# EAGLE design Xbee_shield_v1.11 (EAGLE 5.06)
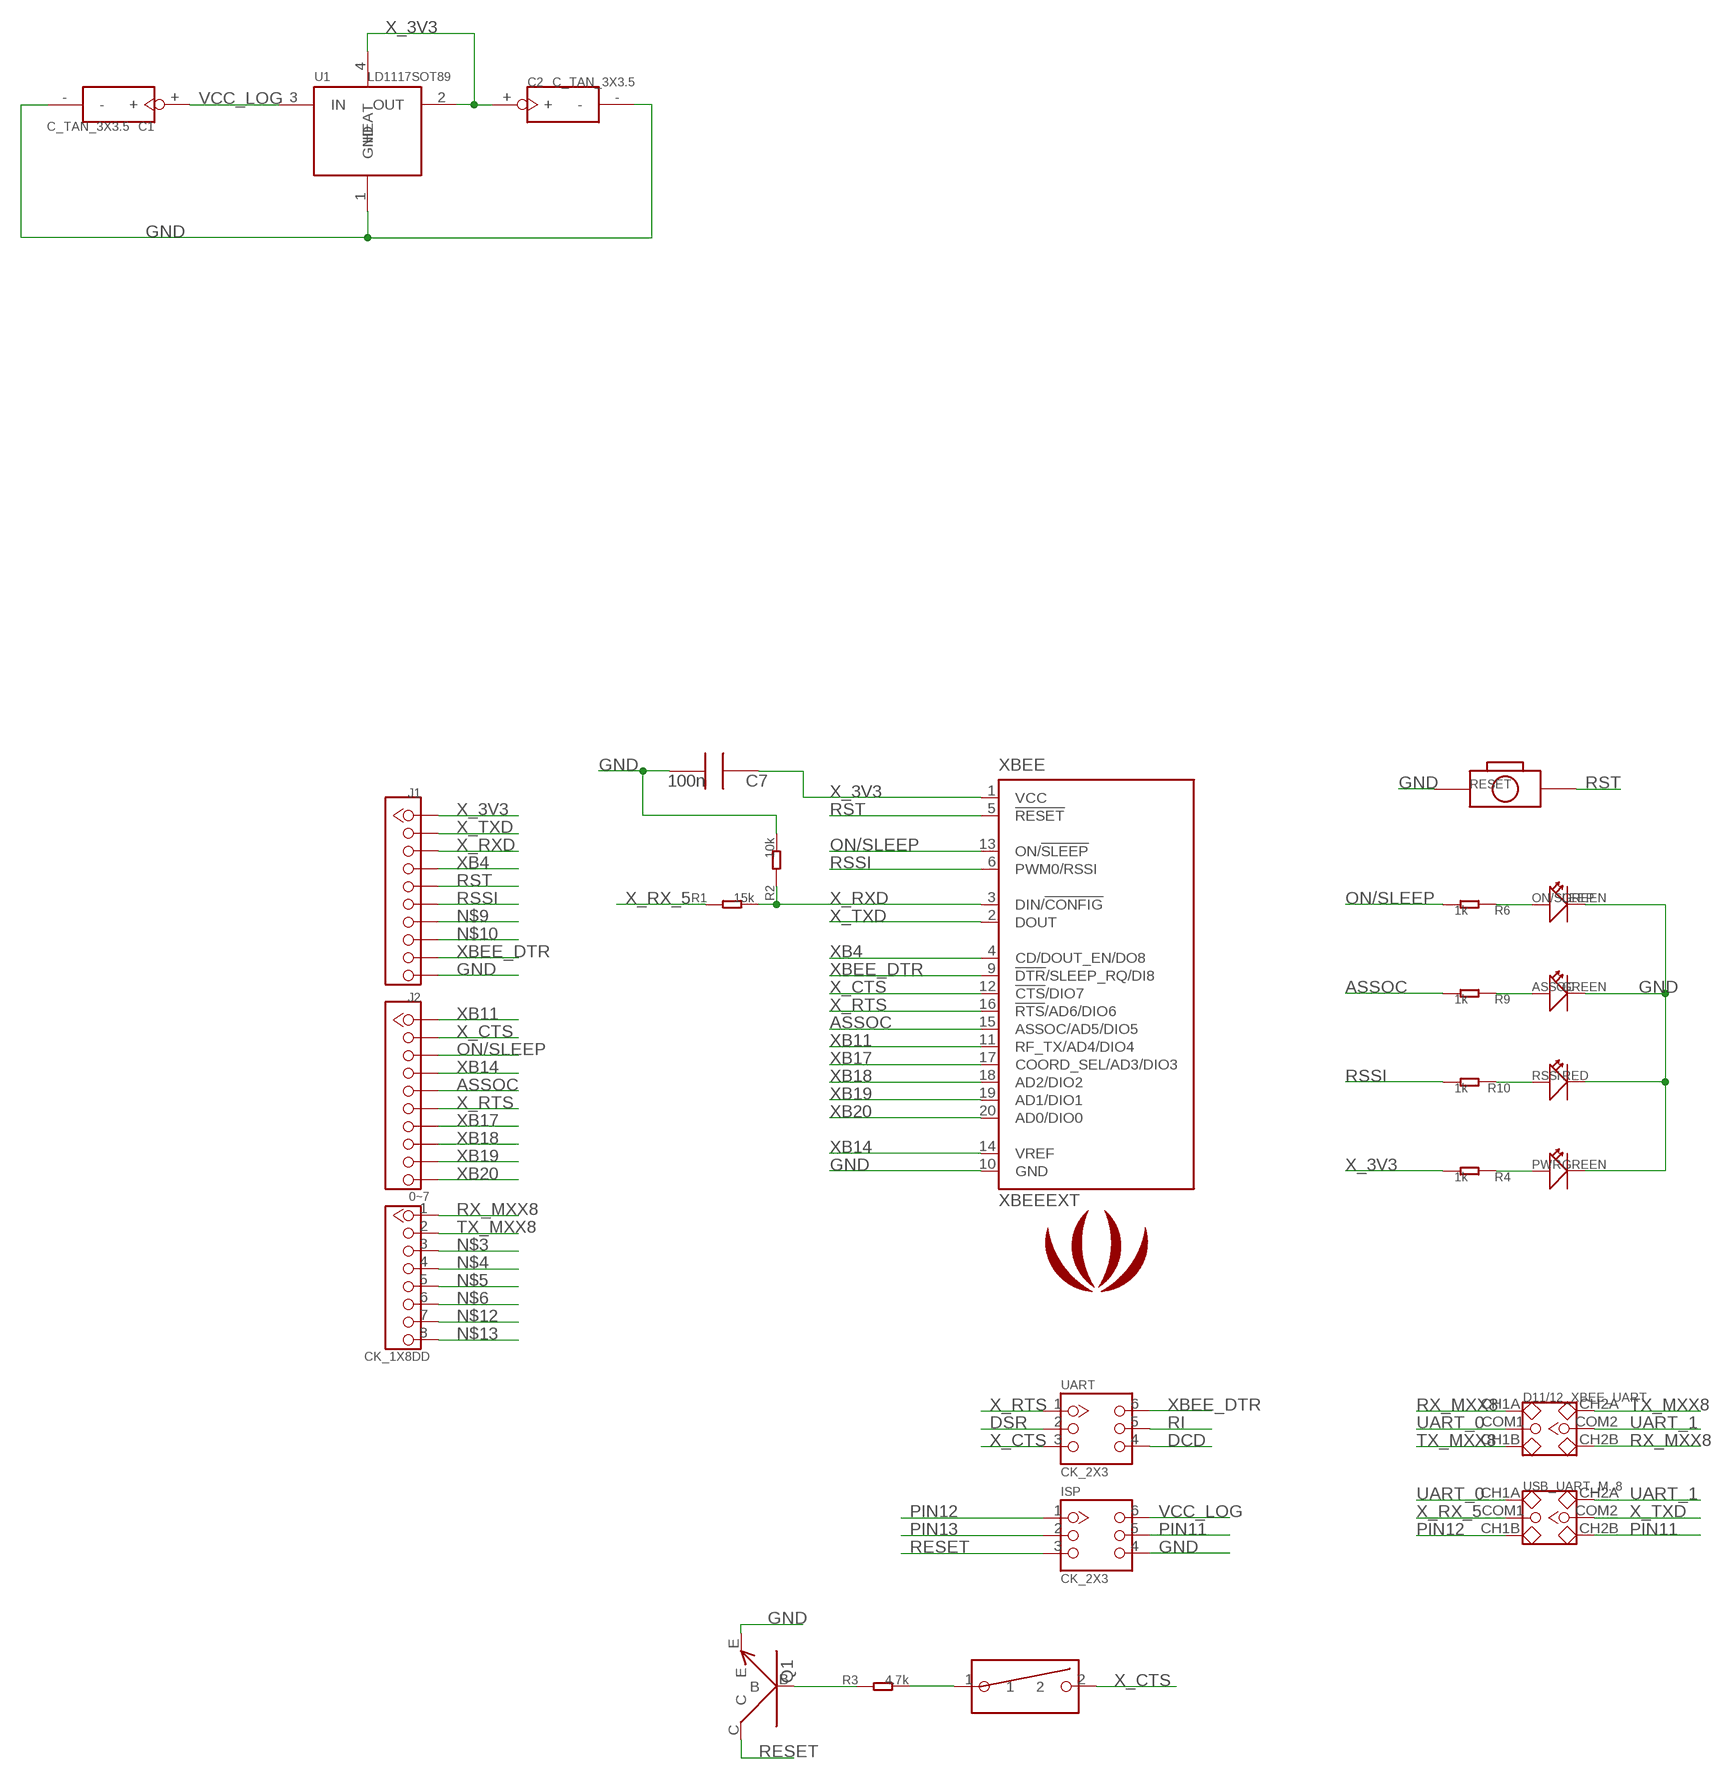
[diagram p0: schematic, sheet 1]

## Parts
0~7  CK_1X8DD  [CK_1X8]
ASSOC  GREEN  LED0603  [LED0603]
C1  C_TAN_3X3.5  [C_TAN_3X3.5]
C2  C_TAN_3X3.5  [C_TAN_3X3.5]
C7  100n  C0603  [0603]
D11/12_XBEE_UART  2.54SW_2CH  [2.54SW_2CH]
ISP  CK_2X3  [CK_2X3_THIN]
J1  CK1X10DD  [CK1X10]
J2  CK1X10DD  [CK1X10]
JP1  SMD_JP  [JP]
LOGO1  LOGO_COPPER200X166  [LOGO_COPPER]
ON/SLEEP  GREEN  LED0603  [LED0603]
PWR  GREEN  LED0603  [LED0603]
Q1  NPN_9013  [SOT23]
R1  15k  R0603  [0603]
R2  10k  R0603  [0603]
R3  4.7k  R0603  [0603]
R4  1k  R0603  [0603]
R6  1k  R0603  [0603]
R9  1k  R0603  [0603]
R10  1k  R0603  [0603]
RESET  BOTTON_1  BOTTON_1_DP  [BTN_5.0_RST]
RSSI  RED  LED0603  [LED0603]
U1  LD1117SOT89  [SOT89]
UART  CK_2X3  [CK_2X3_THIN]
USB_UART_M..8  2.54SW_2CH  [2.54SW_2CH]
XBEE  XBEEEXT  [XBEE_PLUG]

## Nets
ASSOC: J2.5 R9.2 XBEE.15(ASSOC/AD5/DIO5)
DCD: UART.4
DSR: UART.2
GND: ASSOC.2(-) C1.- C2.- C7.2 ISP.4 J1.10 ON/SLEEP.2(-) PWR.2(-) Q1.E R2.2 RESET.P$1 RSSI.2(-) U1.1(GND) XBEE.10(GND)
N$1: Q1.B R3.1
N$2: JP1.1 R3.2
N$3: 0~7.3
N$4: 0~7.4
N$5: 0~7.5
N$6: 0~7.6
N$7: ON/SLEEP.1(+) R6.1
N$8: ASSOC.1(+) R9.1
N$9: J1.7
N$10: J1.8
N$11: R10.1 RSSI.1(+)
N$12: 0~7.7
N$13: 0~7.8
N$14: PWR.1(+) R4.1
ON/SLEEP: J2.3 R6.2 XBEE.13(ON/!SLEEP)
PIN11: ISP.5 USB_UART_M..8.CH2B
PIN12: ISP.1 USB_UART_M..8.CH1B
PIN13: ISP.2
RESET: ISP.3 Q1.C
RI: UART.5
RSSI: J1.6 R10.2 XBEE.6(PWM0/RSSI)
RST: J1.5 RESET.P$2 XBEE.5(!RESET)
RX_MXX8: 0~7.1 D11/12_XBEE_UART.CH1A D11/12_XBEE_UART.CH2B
TX_MXX8: 0~7.2 D11/12_XBEE_UART.CH1B D11/12_XBEE_UART.CH2A
UART_0: D11/12_XBEE_UART.COM1 USB_UART_M..8.CH1A
UART_1: D11/12_XBEE_UART.COM2 USB_UART_M..8.CH2A
VCC_LOG: C1.+ ISP.6 U1.3(IN)
X_3V3: C2.+ C7.1 J1.1 R4.2 U1.2(OUT) U1.4(HEAT) XBEE.1(VCC)
X_CTS: J2.2 JP1.2 UART.3 XBEE.12(!CTS!/DIO7)
X_RTS: J2.6 UART.1 XBEE.16(!RTS!/AD6/DIO6)
X_RX_5: R1.1 USB_UART_M..8.COM1
X_RXD: J1.3 R1.2 R2.1 XBEE.3(DIN/!CONFIG)
X_TXD: J1.2 USB_UART_M..8.COM2 XBEE.2(DOUT)
XB4: J1.4 XBEE.4(CD/DOUT_EN/DO8)
XB11: J2.1 XBEE.11(RF_TX/AD4/DIO4)
XB14: J2.4 XBEE.14(VREF)
XB17: J2.7 XBEE.17(COORD_SEL/AD3/DIO3)
XB18: J2.8 XBEE.18(AD2/DIO2)
XB19: J2.9 XBEE.19(AD1/DIO1)
XB20: J2.10 XBEE.20(AD0/DIO0)
XBEE_DTR: J1.9 UART.6 XBEE.9(!DTR!/SLEEP_RQ/DI8)

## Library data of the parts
0~7 = CONNECTER:CK_1X8
ASSOC ON/SLEEP PWR RSSI = CPT_SMD:LED0603
C1 C2 = CPT_SMD:C_TAN
C7 = CPT_SMD:C0603; C0603: 100N
D11/12_XBEE_UART USB_UART_M..8 = CPT_CJ:2.54SW_2CH
ISP UART = CONNECTER:CK_2X3
J1 J2 = CONNECTER:CK1X10
JP1 = CPT_SMD:SMD_JP
LOGO1 = logo:LOGO_COPPER
Q1 = CPT_SMD:NPN_9013
R1-R4 R6 R9 R10 = CPT_SMD:R0603
RESET = CPT_SMD:BOTTON_1
U1 = ICs_v54:LD1117
XBEE = EXT_moudle:XBEE: XBee (TM) /XBee-PRO(TM) OEM RF Modules Source: MaxStream, Inc. xbee_productmanual.pdf

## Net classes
1 power: width 0.61 mm

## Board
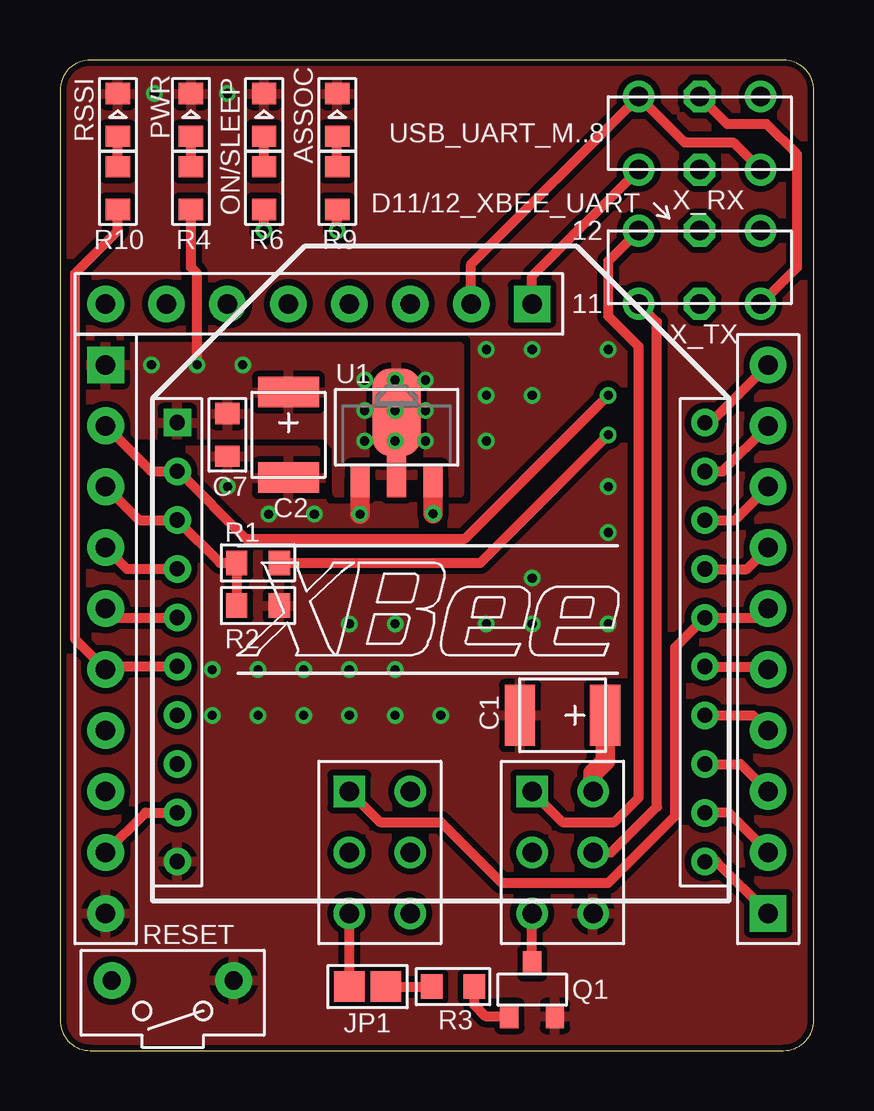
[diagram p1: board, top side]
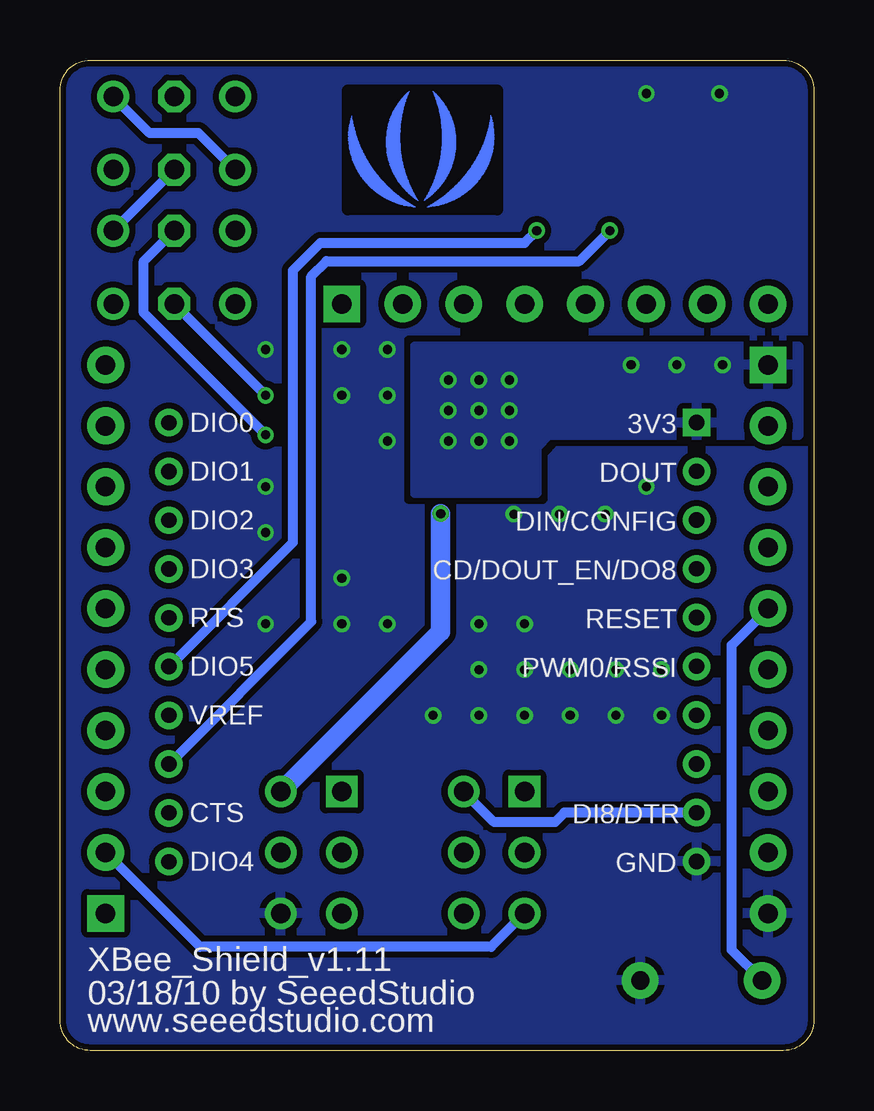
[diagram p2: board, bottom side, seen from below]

Size 31.43 x 41.27 mm. Coordinates in mm from the lower left corner, seen from the top.
Outline: 31.43,40.01 arc90 30.16,41.27 1.27,41.27 arc90 0,40.01 0,1.27 arc90 1.27,0 30.16,0 arc90 31.43,1.27 31.43,40.01
Copper layers (1*16): Top 0.035mm / dielectric 1.5mm / Bottom 0.035mm
Design rules "rule_manufacture": minimum track width 8mil, minimum drill 12mil, track to track 8mil, track to pad 8mil, pad to pad 6mil, via to via 10mil, smd to smd 0mil, copper to edge 10mil, drill to drill 10mil, minimum pad ring 10mil, minimum via ring 6mil, stop-mask expansion 2mil, vias tented up to drill 25mil, thermal gap 10mil
bRestrict: area 13.2,35.1 to 19.4,40

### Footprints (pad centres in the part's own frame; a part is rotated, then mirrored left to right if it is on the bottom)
CK_1X8 = drill 0.813 pad 1.524 square: 1 0,8.89 | drill 0.813 pad 1.524 round: 2 0,6.35; 3 0,3.81; 4 0,1.27; 5 0,-1.27; 6 0,-3.81; 7 0,-6.35; 8 0,-8.89
LED0603 = smd 0.889 x 1.016: 1 -0.889,0; 2 0.889,0
C_TAN_3X3.5 = smd 2.54 x 1.27: + 0,1.778; - 0,-1.778
0603 = smd 0.889 x 1.016: 1 -0.889,0; 2 0.889,0
2.54SW_2CH = drill 0.813 pad 1.27 round: CH1A -1.524,2.54; CH1B -1.524,-2.54; CH2A 1.524,2.54; CH2B 1.524,-2.54 | drill 0.813 pad 1.27 octagon: COM1 -1.524,0; COM2 1.524,0
CK_2X3_THIN = drill 0.813 pad 1.27 square: 1 -1.27,2.54 | drill 0.813 pad 1.27 round: 2 -1.27,0; 3 -1.27,-2.54; 4 1.27,-2.54; 5 1.27,0; 6 1.27,2.54
CK1X10 = drill 0.813 pad 1.524 square: 1 0,11.43 | drill 0.813 pad 1.524 round: 2 0,8.89; 3 0,6.35; 4 0,3.81; 5 0,1.27; 6 0,-1.27; 7 0,-3.81; 8 0,-6.35; 9 0,-8.89; 10 0,-11.43
JP = smd 1.27 x 1.27: 1 -0.762,0; 2 0.762,0
SOT23 = smd 0.762 x 1.016: B -0.95,-1.1; C 0,1.1; E 0.95,-1.1
BTN_5.0_RST = drill 0.762 pad 1.524 round: P$1 0,2.54; P$2 0,-2.54
SOT89 = smd 0.8 x 1.4: 1 -1.524,-1.905; 3 1.524,-1.905 | smd 0.8 x 1.9: 2 0,-1.651 | smd 2.032 x 3.65: 4 0,0.94
XBEE_PLUG = drill 0.635 pad 1.016 square: 1 0,0.008 | drill 0.635 pad 1.016 round: 2 0,-2.024; 3 0,-4.056; 4 0,-6.088; 5 0,-8.12; 6 0,-10.152; 7 0,-12.184; 8 0,-14.216; 9 0,-16.248; 10 0,-18.28; 11 21.996,-18.288; 12 21.996,-16.256; 13 21.996,-14.224; 14 21.996,-12.192; 15 21.996,-10.16; 16 21.996,-8.128; 17 21.996,-6.096; 18 21.996,-4.064; 19 21.996,-2.032; 20 21.996,0

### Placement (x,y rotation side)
0~7  10.79,31.11 270 top
ASSOC  11.56,38.99 90 top
C1  20.95,13.97 270 top
C2  9.53,25.65 0 top
C7  6.99,25.65 270 top
D11/12_XBEE_UART  26.67,38.23 90 top
ISP  20.95,8.26 0 top
J1  1.91,17.14 0 top
J2  29.53,17.14 180 top
JP1  12.83,2.67 180 top
LOGO1  16.38,36.83 0 bottom
ON/SLEEP  8.51,38.99 90 top
PWR  5.46,38.99 90 top
Q1  19.68,2.54 0 top
R1  8.26,20.32 180 top
R2  8.26,18.54 0 top
R3  16.38,2.67 180 top
R4  5.46,35.94 270 top
R6  8.51,35.94 270 top
R9  11.56,35.94 270 top
R10  2.41,35.94 270 top
RESET  4.7,2.92 270 top
RSSI  2.41,38.99 90 top
U1  14.03,25.65 0 top
UART  13.34,8.26 0 top
USB_UART_M..8  26.67,32.64 270 top
XBEE  4.89,26.16 0 top

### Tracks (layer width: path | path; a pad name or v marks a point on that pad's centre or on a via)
ASSOC  (via drill 0.38)
  Top 0.406: XBEE.15 29.4,16 J2.5 | v11.56,34.16 R9.2
  Bottom 0.406: XBEE.15 21.72,21.17 21.72,32.51 20.57,33.66 12.06,33.66 v11.56,34.16
GND  (via drill 0.38)
  Top 0.813: v12.51,22.35 U1.1
  other vias: 6.99,39.88 3.94,39.88 22.86,29.21 17.78,29.21 19.68,29.21 19.68,27.3 17.78,27.3 17.78,25.4 22.86,23.5 22.86,21.59 10.6,22.35 8.7,22.35 6.99,23.5 22.86,17.78 17.78,17.78 19.68,17.78 19.68,19.68 13.97,17.78 12.06,17.78 12.06,15.88 13.97,15.88 13.97,13.97 15.88,13.97 12.06,13.97 10.16,13.97 10.16,15.88 8.26,15.88 6.35,15.88 6.35,13.97 8.26,13.97
  pour Top: -10.79,40.01 -8.89,40.01 -8.89,38.73 -10.79,38.73
  pour Bottom (isolate 0.254, rank 6): 1.27,0 arc-90 0,1.27 0,40.01 arc-90 1.27,41.27 30.16,41.27 arc-90 31.43,40.01 31.43,1.27 arc-90 30.16,0
  pour Top (isolate 0.254, rank 6): 1.27,0 arc-90 0,1.27 0,40.01 arc-90 1.27,41.27 30.16,41.27 arc-90 31.43,40.01 31.43,1.27 arc-90 30.16,0
N$1
  Top 0.406: Q1.B 17.74,1.44 17.27,1.91 R3.1
N$2
  Top 0.406: JP1.1 R3.2
N$7
  Top 0.406: R6.1 ON/SLEEP.1
N$8
  Top 0.406: R9.1 ASSOC.1
N$11
  Top 0.406: R10.1 RSSI.1
N$14
  Top 0.406: R4.1 PWR.1
ON/SLEEP  (via drill 0.38)
  Top 0.406: XBEE.13 28.38,11.94 J2.3 | v8.51,34.16 R6.2
  Bottom 0.406: XBEE.13 20.95,17.87 20.95,32.26 20.32,32.89 9.78,32.89 v8.51,34.16
PIN11
  Top 0.406: ISP.5 22.99,8.26 24.89,10.16 24.89,30.35 USB_UART_M..8.CH2B
PIN12
  Top 0.406: ISP.1 20.95,9.53 23.11,9.53 24.13,10.54 24.13,29.34 22.86,30.61 22.86,32.89 USB_UART_M..8.CH1B
RESET
  Top 0.406: Q1.C ISP.3
RSSI
  Top 0.406: XBEE.6 2.04,16.01 J1.6 0.64,17.14 0.64,32.38 2.41,34.16 R10.2
RST
  Top 0.406: XBEE.5 2.28,18.04 J1.5
  Bottom 0.406: RESET.P$2 3.43,4.19 3.43,16.89 J1.5
RX_MXX8
  Top 0.406: 0~7.1 19.68,32.26 D11/12_XBEE_UART.CH1A
  Bottom 0.406: D11/12_XBEE_UART.CH1A 25.65,38.23 27.69,38.23 D11/12_XBEE_UART.CH2B
TX_MXX8
  Top 0.406: D11/12_XBEE_UART.CH1B 28.07,37.85 26.04,37.85 D11/12_XBEE_UART.CH2A 17.14,32.77 0~7.2
UART_0
  Bottom 0.406: USB_UART_M..8.CH1A D11/12_XBEE_UART.COM1
UART_1
  Top 0.406: USB_UART_M..8.CH2A 30.73,32.64 30.73,37.34 29.46,38.61 27.81,38.61 D11/12_XBEE_UART.COM2
VCC_LOG  (via drill 0.38)
  Top 0.813: ISP.6 22.23,11.56 22.73,12.06 C1.+ | v15.56,22.38 U1.3
  Bottom 0.813: ISP.6 15.56,17.46 v15.56,22.38
X_3V3  (via drill 0.38)
  Top 0.406: R4.2 5.46,32.64 5.71,32.38 v5.71,28.57
  other vias: 3.81,28.57 7.62,28.57 13.97,27.94 13.97,26.67 13.97,25.4 12.7,26.67 15.24,26.67 12.7,27.94 15.24,27.94 12.7,25.4 15.24,25.4
  pour Bottom (isolate 0.254): 0.64,29.34 16.64,29.34 16.64,23.24 11.56,23.24 11.56,25.14 11.05,25.65 0.64,25.65
  pour Top (isolate 0.254): 0.64,29.34 16.64,29.34 16.64,23.24 11.56,23.24 11.56,25.14 11.05,25.65 0.64,25.65
X_CTS
  Top 0.406: XBEE.12 27.88,9.91 J2.2 | JP1.2 UART.3
  Bottom 0.406: UART.3 13.46,4.32 25.59,4.32 J2.2
X_RTS
  Top 0.406: J2.6 29.15,18.03 XBEE.16 25.65,16.8 25.65,9.78 22.86,6.99 18.41,6.99 15.88,9.53 13.34,9.53 UART.1
X_RX_5  (via drill 0.38)
  Top 0.406: R1.1 17.53,20.32 v22.86,25.65
  Bottom 0.406: v22.86,25.65 27.94,30.73 27.94,32.89 USB_UART_M..8.COM1
X_RXD
  Top 0.406: J1.3 3.29,22.11 XBEE.3 6.67,20.32 R1.2 R2.1
X_TXD  (via drill 0.38)
  Top 0.406: J1.2 3.8,24.14 XBEE.2 4.95,24.14 7.75,21.34 16.89,21.34 v22.86,27.3
  Bottom 0.406: v22.86,27.3 USB_UART_M..8.COM2
XB4
  Top 0.406: XBEE.4 2.79,20.07 J1.4
XB11
  Top 0.406: XBEE.11 27.37,7.87 J2.1
XB14
  Top 0.406: XBEE.14 28.89,13.97 J2.4
XB17
  Top 0.406: XBEE.17 28.64,20.07 J2.7
XB18
  Top 0.406: XBEE.18 28.13,22.1 J2.8
XB19
  Top 0.406: XBEE.19 27.62,24.13 J2.9
XB20
  Top 0.406: XBEE.20 27.11,26.16 J2.10
XBEE_DTR
  Top 0.406: XBEE.9 3.56,9.91 J1.9
  Bottom 0.406: XBEE.9 10.41,9.91 10.79,9.53 13.34,9.53 UART.6

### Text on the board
Top: top layer
Bottom: bottom layer
Dimension: boardoutline
tPlace: silktop | X_RX | 12 | 11 | X_TX
bPlace: silkbottom | 3V3 | DIO0 | DOUT | DIO1 | DIN/CONFIG | DIO2 | CD/DOUT_EN/DO8 | DIO3 | RESET | RTS | PWM0/RSSI | DIO5 | VREF | DI8/DTR | CTS | GND | DIO4 | XBee_Shield_v1.11 | 03/18/10 by SeeedStudio | www.seeedstudio.com
tStop: soldermask top
bStop: soldermask bottom
tCream: padmask top
bCream: padmask bottom
Drills: drill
